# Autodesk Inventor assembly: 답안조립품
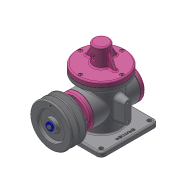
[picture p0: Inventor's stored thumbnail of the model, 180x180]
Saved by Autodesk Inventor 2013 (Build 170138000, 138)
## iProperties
Created: 2020-02
Part Number: 답안조립품
Document SubType Name: Assembly
Designer: Administrator
Mass: 2563.02 g
Surface Area: 2485.57 cm^2
Volume: 789.818 cm^3
Density: 3.24508 g/cm^3
Author: Administrator
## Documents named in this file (21)
- C:\Users\Administrator\Desktop\600206V1011\600206V1011\답안조립품.iam
- C:\Users\Administrator\Desktop\600206V1011\600206V1011\본체.ipt
- C:\Users\Administrator\Desktop\600206V1011\600206V1011\E-링.ipt
- C:\Users\Administrator\Desktop\600206V1011\600206V1011\V-벨트풀리.ipt
- C:\Users\Administrator\Desktop\600206V1011\600206V1011\가변스프링.ipt
- C:\Users\Administrator\Desktop\600206V1011\600206V1011\개스킷 A.ipt
- C:\Users\Administrator\Desktop\600206V1011\600206V1011\개스킷 B.ipt
- C:\Users\Administrator\Desktop\600206V1011\600206V1011\덮개.ipt
- C:\Users\Administrator\Desktop\600206V1011\600206V1011\뒤커버.ipt
- C:\Users\Administrator\Desktop\600206V1011\600206V1011\링크.ipt
- C:\Users\Administrator\Desktop\600206V1011\600206V1011\베어링 17 x 40 x 12.ipt
- C:\Users\Administrator\Desktop\600206V1011\600206V1011\볼트 M4 x 10.ipt
- C:\Users\Administrator\Desktop\600206V1011\600206V1011\슬라이더.ipt
- C:\Users\Administrator\Desktop\600206V1011\600206V1011\앞커버.ipt
- C:\Users\Administrator\Desktop\600206V1011\600206V1011\오일 실 17 30 8.ipt
- C:\Users\Administrator\Desktop\600206V1011\600206V1011\와셔 4x16.ipt
- C:\Users\Administrator\Desktop\600206V1011\600206V1011\육각 소켓 머리 볼트 M4 x 10.ipt
- C:\Users\Administrator\Desktop\600206V1011\600206V1011\클레비스 핀 6 x 22.ipt
- 클레비스 핀 6 x 22.ipt
- C:\Users\Administrator\Desktop\600206V1011\600206V1011\키 4 x 4 x 25.ipt
- C:\Users\Administrator\Desktop\600206V1011\600206V1011\편심축.ipt
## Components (6 placed, 5 different names)
1. E-링:1
2. V-벨트풀리:1 — 각도:2
3. 개스킷 A:1
4. 개스킷 B:1
5. 개스킷 A:2
6. 가변스프링:1
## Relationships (1: Angle 1)
- 각도:2 [Angle]: V-벨트풀리:1
